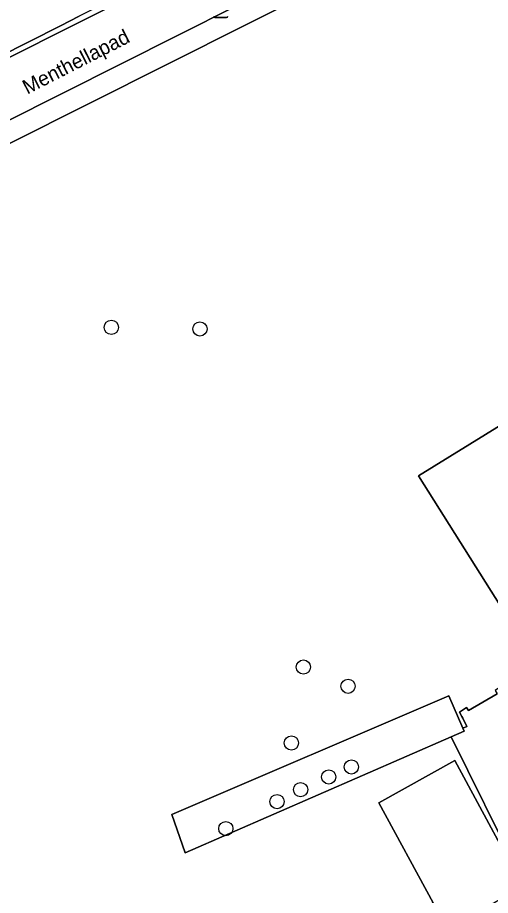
# Model space of a CAD drawing. Extents: x 162344 to 162869, y 381217 to 381818.
# Drawn here: x 162516.9 to 162549.4, y 381421.8 to 381482.2 of the extents above; entities that cross this region are included whole.
import ezdxf

# ---------------------------------------------------------------- set-up
doc = ezdxf.new("R2010")
doc.units = 0
for name, color, linetype in [('IMGEO_Boom', 7, 'Continuous'), ('IMGEO_Erf', 7, 'Continuous'), ('IMGEO_Groenvoorziening', 7, 'Continuous'), ('IMGEO_Lichtmast', 7, 'Continuous'), ('IMGEO_Openbare_ruimte_label', 7, 'Continuous'), ('IMGEO_Parkeervlak_open', 7, 'Continuous'), ('IMGEO_Rijbaan_lokaal_gesloten', 7, 'Continuous'), ('IMGEO_Voetpad_open', 7, 'Continuous')]:
    doc.layers.add(name, color=color, linetype=linetype)

msp = doc.modelspace()

# ---------------------------------------------------------------- linework, layer by layer
at = {"layer": 'IMGEO_Boom'}
for centre in [(162523.337, 381460.878), (162529.433, 381460.769), (162536.548, 381437.529), (162539.624, 381436.21), (162535.725, 381432.308), (162539.849, 381430.664), (162538.293, 381429.975), (162536.354, 381429.101), (162534.734, 381428.277), (162531.21, 381426.425)]:
    msp.add_circle(centre, 0.489, dxfattribs=at)
at = {"layer": 'IMGEO_Erf'}
msp.add_lwpolyline([(162622.037, 381407.841), (162605.841, 381425.165), (162603.922, 381427.994), (162596.425, 381439.548), (162594.828, 381442.012), (162591.287, 381447.468), (162588.885, 381451.187), (162575.654, 381472.131), (162574.139, 381474.467), (162572.367, 381477.268), (162564.943, 381472.596), (162566.7, 381469.803), (162563.061, 381467.513), (162561.304, 381470.306), (162550.724, 381463.648), (162554.763, 381457.01), (162544.461, 381450.664), (162552.634, 381437.722), (162563.756, 381419.355)], dxfattribs=at)
at = {"layer": 'IMGEO_Groenvoorziening'}
for points in [[(162474.364, 381504.517), (162490.097, 381473.002), (162492.37, 381474.118), (162493.498, 381474.638), (162495.941, 381469.56), (162500, 381471.606), (162503.84, 381473.541), (162507.027, 381475.147), (162519.835, 381481.603), (162521.134, 381482.258)], [(162560.659, 381495.777), (162538.071, 381484.442), (162500, 381465.338), (162494.068, 381462.441), (162496.664, 381457.154), (162501.075, 381448.315), (162501.325, 381448.372), (162502.674, 381445.558), (162502.662, 381445.418), (162512.923, 381424.22), (162515.697, 381418.727)], [(162552.634, 381437.722), (162544.461, 381450.664), (162554.763, 381457.01)], [(162551.316, 381423.428), (162546.716, 381432.738), (162528.414, 381424.756), (162527.509, 381427.397), (162546.558, 381435.544)], [(162546.558, 381435.544), (162547.509, 381433.329), (162547.8, 381433.443), (162547.525, 381434.003), (162547.44, 381434.134), (162547.291, 381434.43), (162547.779, 381434.758), (162547.898, 381434.544), (162549.879, 381435.692)]]:
    msp.add_lwpolyline(points, dxfattribs=at)
for points in [[(162500, 381465.338), (162538.071, 381484.442), (162560.659, 381495.777), (162559.862, 381497.036), (162500, 381466.932), (162494.61, 381464.221), (162494.068, 381462.441)], [(162520.002, 381481.273), (162549.3, 381495.97), (162549.397, 381496.018), (162549.201, 381496.403), (162543.007, 381493.282), (162528.998, 381486.221), (162521.134, 381482.258), (162519.835, 381481.603), (162507.027, 381475.147), (162507.173, 381474.837)], [(162546.716, 381432.738), (162547.598, 381433.122), (162547.509, 381433.329), (162546.558, 381435.544), (162527.509, 381427.397), (162528.414, 381424.756)], [(162545.47, 381421.311), (162541.728, 381428.198), (162546.973, 381431.115), (162551.651, 381422.432), (162536.054, 381413.606), (162534.87, 381415.667)]]:
    msp.add_lwpolyline(points, close=True, dxfattribs=at)
at = {"layer": 'IMGEO_Lichtmast'}
for p, q in [((162531.253, 381482.173), (162530.463, 381482.173)), ((162530.463, 381482.173), (162531.253, 381482.173))]:
    msp.add_line(p, q, dxfattribs=at)
for centre, start, end in [((162530.463, 381482.273), 180, 270), ((162530.463, 381482.273), 180, 270), ((162531.253, 381482.273), 270, 0), ((162531.253, 381482.273), 270, 0)]:
    msp.add_arc(centre, 0.1, start, end, dxfattribs=at)
at = {"layer": 'IMGEO_Parkeervlak_open'}
msp.add_lwpolyline([(162546.973, 381431.115), (162541.728, 381428.198), (162545.47, 381421.311), (162534.87, 381415.667), (162536.054, 381413.606), (162551.651, 381422.432)], close=True, dxfattribs=at)
at = {"layer": 'IMGEO_Rijbaan_lokaal_gesloten'}
msp.add_lwpolyline([(162550.185, 381436.215), (162549.738, 381435.916), (162549.879, 381435.692), (162547.898, 381434.544), (162547.779, 381434.758), (162547.291, 381434.43), (162547.44, 381434.134), (162547.525, 381434.003), (162547.8, 381433.443), (162547.509, 381433.329), (162547.598, 381433.122), (162546.716, 381432.738), (162551.316, 381423.428)], dxfattribs=at)
at = {"layer": 'IMGEO_Voetpad_open'}
msp.add_lwpolyline([(162549.3, 381495.97), (162520.002, 381481.273), (162507.173, 381474.837), (162503.991, 381473.241), (162500, 381471.234), (162496.084, 381469.265), (162495.02, 381468.72), (162492.747, 381467.604), (162491.536, 381466.979), (162488.025, 381465.214), (162482.458, 381462.415), (162471.586, 381456.911), (162466.79, 381454.429), (162469.085, 381449.938), (162472.642, 381451.739), (162480.771, 381455.855), (162480.915, 381455.761), (162483.626, 381457.134), (162491.815, 381461.335), (162494.068, 381462.441), (162494.61, 381464.221), (162500, 381466.932), (162559.862, 381497.036)], dxfattribs=at)

# ---------------------------------------------------------------- texts
at = {"layer": 'IMGEO_Openbare_ruimte_label'}
msp.add_text('Menthellapad', height=1, rotation=27.05168, dxfattribs=at).set_placement((162517.551, 381476.869))

doc.saveas('drawing.dxf')
